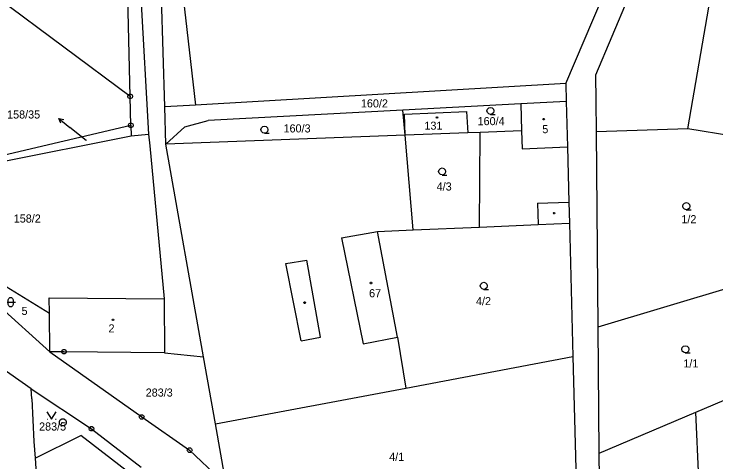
# Model space of a CAD drawing. Extents: x -780000 to -777378, y -1011169 to -1009297.
# Drawn here: x -779250.3 to -779102.6, y -1010218.8 to -1010124.6 of the extents above; entities that cross this region are included whole.
import ezdxf

# ---------------------------------------------------------------- set-up
doc = ezdxf.new("R2010")
doc.units = 0
for name, color, linetype in [('Default', 7, 'Continuous'), ('KN_HRANICE', 7, 'Continuous'), ('KN_KULTURY', 7, 'Continuous'), ('KN_PARCELY', 7, 'Continuous'), ('KN_SLUCKY', 7, 'Continuous')]:
    doc.layers.add(name, color=color, linetype=linetype)

# ---------------------------------------------------------------- blocks, each defined once
blk = doc.blocks.new('101')
at = {"layer": 'Default'}
blk.add_line((-0.05, 0), (0.05, 0), dxfattribs=at)
blk.add_lwpolyline([(0.19, 0.72), (0.53, 0.53), (0.72, 0.19), (0.72, -0.2), (0.53, -0.54), (0.19, -0.73), (-0.2, -0.73), (-0.54, -0.54), (-0.73, -0.2), (-0.73, 0.19), (-0.54, 0.53), (-0.2, 0.72), (0.19, 0.72)], dxfattribs=at)
blk = doc.blocks.new('304')
at = {"layer": 'Default'}
blk.add_lwpolyline([(0, 0), (-0.38, 0.1), (-0.65, 0.37), (-0.75, 0.74), (-0.65, 1.11), (-0.38, 1.38), (-0.01, 1.48), (0.36, 1.38), (0.63, 1.11), (0.73, 0.73), (0.63, 0.35), (0.36, 0.08), (-0.02, -0.02), (0.98, -0.02)], dxfattribs=at)
blk = doc.blocks.new('314')
at = {"layer": 'Default'}
for p, q in [((-0.95, 0), (-0.85, 0)), ((0.85, 0), (0.95, 0))]:
    blk.add_line(p, q, dxfattribs=at)
blk.add_lwpolyline([(-1, 1.5), (0, 0), (1, 1.5)], dxfattribs=at)
blk = doc.blocks.new('316')
at = {"layer": 'Default'}
for points in [[(-0.5, 1.5), (-0.4, 1.79), (-0.15, 1.97), (0.16, 1.97), (0.41, 1.79), (0.51, 1.5), (0.51, 0.5), (0.41, 0.21), (0.16, 0.03), (-0.15, 0.03), (-0.4, 0.21), (-0.5, 0.5), (-0.5, 1.5)], [(-1, 1), (0.27, 1), (1, 1)]]:
    blk.add_lwpolyline(points, dxfattribs=at)
blk = doc.blocks.new('10292')
at = {"layer": 'Default'}
blk.add_line((0, 3), (0, 0), dxfattribs=at)
blk.add_lwpolyline([(-0.5, 2), (0, 3), (0.5, 2)], dxfattribs=at)
blk = doc.blocks.new('402')
at = {"layer": 'Default'}
blk.add_lwpolyline([(0.09, 0.15), (0.18, 0), (0.09, -0.15), (-0.09, -0.15), (-0.18, 0), (-0.09, 0.15), (0.09, 0.15)], dxfattribs=at)
blk = doc.blocks.new('105')
at = {"layer": 'Default'}
blk.add_line((-0.12, 0), (0.12, 0), dxfattribs=at)
blk.add_lwpolyline([(0.15, 0.48), (0.4, 0.3), (0.5, 0.01), (0.4, -0.28), (0.15, -0.46), (-0.16, -0.46), (-0.41, -0.28), (-0.51, 0.01), (-0.41, 0.3), (-0.16, 0.48), (0.15, 0.48)], dxfattribs=at)

msp = doc.modelspace()

# ---------------------------------------------------------------- linework, layer by layer
at = {"layer": 'KN_HRANICE'}
for p, q in [((-779218.82, -1010085.26), (-779212.16, -1010143.8)), ((-779218.61, -1010144.17), (-779219.75, -1010106.05)), ((-779134.25, -1010139.27), (-779120.37, -1010106.68)), ((-779224.22, -1010110.43), (-779222.02, -1010149.91)), ((-779225.9, -1010141.96), (-779262.32, -1010114.82)), ((-779225.9, -1010141.96), (-779226.51, -1010114.99)), ((-779127.92, -1010137.41), (-779118.39, -1010114.83)), ((-779127.87, -1010142.99), (-779127.92, -1010137.41)), ((-779134.25, -1010139.27), (-779212.16, -1010143.8)), ((-779134.25, -1010139.27), (-779134.15, -1010143.02)), ((-779225.76, -1010148.05), (-779225.9, -1010141.96)), ((-779134.15, -1010143.02), (-779143.73, -1010143.53)), ((-779134.15, -1010143.02), (-779133.9, -1010152.56)), ((-779127.81, -1010149.44), (-779127.87, -1010142.99)), ((-779212.16, -1010143.8), (-779218.61, -1010144.17)), ((-779218.39, -1010152.01), (-779218.61, -1010144.17)), ((-779168.53, -1010144.84), (-779209.48, -1010147.01)), ((-779143.73, -1010143.53), (-779168.53, -1010144.84)), ((-779168.07, -1010150.12), (-779168.53, -1010144.84)), ((-779143.73, -1010143.53), (-779143.53, -1010149.2)), ((-779168.2, -1010145.69), (-779155.14, -1010145.17)), ((-779168.07, -1010150.12), (-779168.2, -1010145.69)), ((-779155.14, -1010145.17), (-779154.88, -1010149.63)), ((-779214.4, -1010148.33), (-779209.48, -1010147.01)), ((-779225.76, -1010148.05), (-779265.87, -1010157.54)), ((-779225.76, -1010148.05), (-779225.71, -1010150.28)), ((-779218.39, -1010152.01), (-779214.4, -1010148.33)), ((-779143.53, -1010149.2), (-779152.27, -1010149.53)), ((-779108.53, -1010148.76), (-779127.81, -1010149.44)), ((-779096.36, -1010150.77), (-779108.53, -1010148.76)), ((-779283.36, -1010161.68), (-779225.71, -1010150.28)), ((-779225.71, -1010150.28), (-779222.02, -1010149.91)), ((-779222.02, -1010149.91), (-779221.79, -1010152.36)), ((-779168.07, -1010150.12), (-779218.39, -1010152.01)), ((-779154.88, -1010149.63), (-779168.07, -1010150.12)), ((-779166.33, -1010170.02), (-779168.07, -1010150.12)), ((-779152.27, -1010149.53), (-779154.88, -1010149.63)), ((-779152.43, -1010169.43), (-779152.27, -1010149.53)), ((-779127.44, -1010190.39), (-779127.81, -1010149.44)), ((-779210.46, -1010196.74), (-779218.39, -1010152.01)), ((-779221.79, -1010152.36), (-779218.76, -1010184.53)), ((-779133.9, -1010152.56), (-779133.6, -1010164.22)), ((-779133.6, -1010164.22), (-779133.49, -1010168.63)), ((-779173.84, -1010170.34), (-779166.33, -1010170.02)), ((-779166.33, -1010170.02), (-779152.43, -1010169.43)), ((-779152.43, -1010169.43), (-779140.08, -1010168.91)), ((-779140.08, -1010168.91), (-779133.49, -1010168.63)), ((-779133.49, -1010168.63), (-779132.76, -1010196.68)), ((-779169.66, -1010192.59), (-779173.84, -1010170.34)), ((-779254.75, -1010180.24), (-779242.9, -1010187.56)), ((-779127.44, -1010190.39), (-779090.53, -1010179.36)), ((-779257.16, -1010182.76), (-779242.79, -1010195.65)), ((-779242.94, -1010184.31), (-779218.76, -1010184.53)), ((-779242.9, -1010187.56), (-779242.94, -1010184.31)), ((-779218.76, -1010184.53), (-779218.67, -1010195.92)), ((-779242.79, -1010195.65), (-779242.9, -1010187.56)), ((-779127.2, -1010217), (-779127.44, -1010190.39)), ((-779246.71, -1010203.46), (-779262.24, -1010192.63)), ((-779169.66, -1010192.59), (-779167.91, -1010203.3)), ((-779242.79, -1010195.65), (-779223.48, -1010209.38)), ((-779239.83, -1010195.66), (-779242.79, -1010195.65)), ((-779218.67, -1010195.92), (-779239.83, -1010195.66)), ((-779218.67, -1010195.92), (-779210.46, -1010196.74)), ((-779207.96, -1010210.85), (-779210.46, -1010196.74)), ((-779167.91, -1010203.3), (-779132.76, -1010196.68)), ((-779132.76, -1010196.68), (-779132.14, -1010220.3)), ((-779106.91, -1010208.39), (-779091.64, -1010201.91)), ((-779246.59, -1010205.57), (-779246.71, -1010203.46)), ((-779246.71, -1010203.46), (-779234.04, -1010211.86)), ((-779207.96, -1010210.85), (-779167.91, -1010203.3)), ((-779246.59, -1010205.57), (-779246.15, -1010214.51)), ((-779127.2, -1010217), (-779106.91, -1010208.39)), ((-779106.16, -1010223.74), (-779106.91, -1010208.39)), ((-779223.48, -1010209.38), (-779213.39, -1010216.37)), ((-779205.69, -1010223.63), (-779207.96, -1010210.85)), ((-779234.04, -1010211.86), (-779223.57, -1010219.94)), ((-779245.92, -1010218.02), (-779236.27, -1010213.3)), ((-779225.85, -1010221.36), (-779236.27, -1010213.3)), ((-779246.15, -1010214.51), (-779245.92, -1010218.02)), ((-779213.39, -1010216.37), (-779205.69, -1010223.63)), ((-779127.06, -1010232.92), (-779127.2, -1010217)), ((-779245.92, -1010218.02), (-779245.13, -1010229.97))]:
    msp.add_line(p, q, dxfattribs=at)
at = {"layer": 'KN_PARCELY'}
msp.add_line((-779235.13, -1010151.25), (-779238.59, -1010148.48), dxfattribs=at)
at = {"layer": 'KN_SLUCKY'}
for p, q in [((-779108.53, -1010148.76), (-779103.38, -1010118.93)), ((-779143.53, -1010149.2), (-779143.39, -1010153)), ((-779143.39, -1010153), (-779133.9, -1010152.56)), ((-779140.21, -1010164.42), (-779133.6, -1010164.22)), ((-779140.21, -1010164.42), (-779140.08, -1010168.91)), ((-779181.46, -1010171.71), (-779173.84, -1010170.34)), ((-779181.46, -1010171.71), (-779176.88, -1010194.03)), ((-779193.17, -1010177.11), (-779188.72, -1010176.41)), ((-779189.9, -1010193.37), (-779193.17, -1010177.11)), ((-779185.87, -1010192.57), (-779188.72, -1010176.41)), ((-779189.9, -1010193.37), (-779185.87, -1010192.57)), ((-779176.88, -1010194.03), (-779169.66, -1010192.59))]:
    msp.add_line(p, q, dxfattribs=at)

# ---------------------------------------------------------------- block references
at = {"layer": 'KN_KULTURY'}
for name, p in [('304', (-779150.08, -1010145.74)), ('402', (-779161.34, -1010146.42)), ('402', (-779138.89, -1010146.76)), ('304', (-779197.64, -1010149.69)), ('304', (-779160.25, -1010158.48)), ('304', (-779108.86, -1010165.78)), ('402', (-779136.69, -1010166.53)), ('402', (-779175.24, -1010181.2)), ('304', (-779151.49, -1010182.54)), ('316', (-779251.04, -1010186.22)), ('402', (-779189.2, -1010185.33)), ('402', (-779229.51, -1010188.95)), ('304', (-779109.08, -1010195.88)), ('314', (-779242.45, -1010209.81))]:
    msp.add_blockref(name, p, dxfattribs=at)
at = {"layer": 'KN_PARCELY'}
for name, p in [('105', (-779225.9, -1010141.96)), ('105', (-779225.76, -1010148.05)), ('105', (-779239.83, -1010195.66)), ('101', (-779240.07, -1010210.52)), ('105', (-779223.48, -1010209.38)), ('105', (-779234.04, -1010211.86)), ('105', (-779213.39, -1010216.37))]:
    msp.add_blockref(name, p, dxfattribs=at)
at = {"layer": 'KN_PARCELY', "rotation": 51.33701799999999}
msp.add_blockref('10292', (-779238.59, -1010148.48), dxfattribs=at)

# ---------------------------------------------------------------- texts
at = {"layer": 'KN_PARCELY'}
for s, height, p in [('160/2', 1.7, (-779177.35, -1010144.28)), ('158/35', 1.7, (-779251.8, -1010146.61)), ('160/4', 1.7, (-779152.8, -1010148.01)), ('160/3', 1.7, (-779193.63, -1010149.54)), ('131', 1.7, (-779163.99, -1010148.96)), ('5', 1.7, (-779139.18, -1010149.7)), ('158/35', 0.1, (-779235.11, -1010151.25)), ('4/3', 1.7, (-779161.41, -1010161.75)), ('158/2', 1.7, (-779250.4, -1010168.49)), ('1/2', 1.7, (-779109.92, -1010168.63)), ('67', 1.7, (-779175.63, -1010184.2)), ('4/2', 1.7, (-779153.14, -1010185.86)), ('5', 1.7, (-779248.76, -1010187.92)), ('2', 1.7, (-779230.46, -1010191.59)), ('1/1', 1.7, (-779109.5, -1010198.96)), ('283/3', 1.7, (-779222.64, -1010205.09)), ('283/5', 1.7, (-779245.07, -1010212.23)), ('4/1', 1.7, (-779171.4, -1010218.61))]:
    msp.add_text(s, height=height, dxfattribs=at).set_placement(p)

doc.saveas('drawing.dxf')
